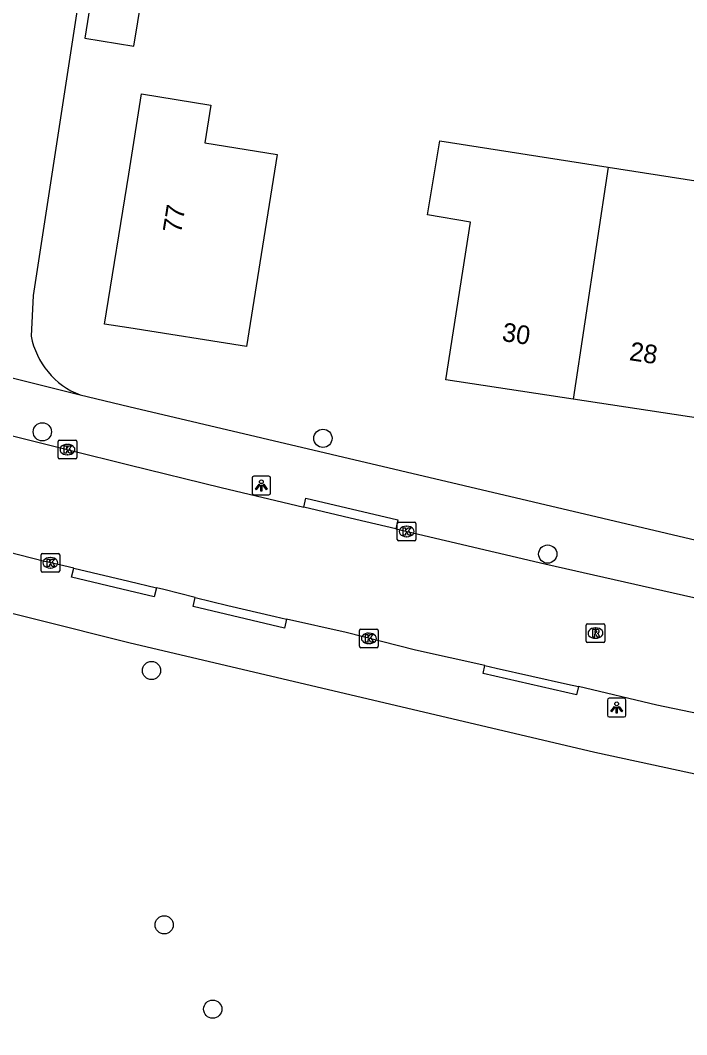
# Model space of a CAD drawing. Extents: x 161486 to 162249, y 379484 to 380829.
# Drawn here: x 161994.2 to 162029.9, y 380361 to 380415.4 of the extents above; entities that cross this region are included whole.
import ezdxf

# ---------------------------------------------------------------- set-up
doc = ezdxf.new("R2010")
doc.units = 0
for name, color, linetype in [('IMGEO_Boom', 7, 'Continuous'), ('IMGEO_Kolk', 7, 'Continuous'), ('IMGEO_Lichtpunt', 7, 'Continuous'), ('IMGEO_Pand', 7, 'Continuous'), ('IMGEO_Pand_nummerreeks', 7, 'Continuous'), ('IMGEO_Rijbaan_lokaal_open', 7, 'Continuous'), ('IMGEO_Rioolput', 7, 'Continuous'), ('IMGEO_Voetpad_open', 7, 'Continuous')]:
    doc.layers.add(name, color=color, linetype=linetype)

msp = doc.modelspace()

# ---------------------------------------------------------------- linework, layer by layer
at = {"layer": 'IMGEO_Boom'}
for centre in [(161995.365, 380393.337), (162010.417, 380392.989), (162022.476, 380386.782), (162001.224, 380380.539), (162001.905, 380366.904), (162004.508, 380362.385)]:
    msp.add_circle(centre, 0.489, dxfattribs=at)
at = {"layer": 'IMGEO_Kolk'}
for p, q in [((161996.291, 380392.884), (161997.143, 380392.884)), ((161996.216, 380391.958), (161996.216, 380392.81)), ((161996.704, 380392.664), (161996.729, 380392.664)), ((161997.217, 380392.81), (161997.217, 380391.958)), ((161997.143, 380391.884), (161996.291, 380391.884)), ((161996.727, 380392.104), (161996.702, 380392.104)), ((162014.407, 380387.569), (162014.407, 380388.421)), ((162014.482, 380388.495), (162015.334, 380388.495)), ((162014.895, 380388.275), (162014.92, 380388.275)), ((162015.408, 380388.421), (162015.408, 380387.569)), ((162015.334, 380387.495), (162014.482, 380387.495)), ((162014.918, 380387.715), (162014.893, 380387.715)), ((161995.3, 380385.889), (161995.3, 380386.741)), ((161995.375, 380386.815), (161996.227, 380386.815)), ((161995.788, 380386.595), (161995.813, 380386.595)), ((161996.301, 380386.741), (161996.301, 380385.889)), ((161996.227, 380385.815), (161995.375, 380385.815)), ((161995.811, 380386.035), (161995.786, 380386.035)), ((162012.381, 380381.837), (162012.381, 380382.689)), ((162012.456, 380382.763), (162013.308, 380382.763)), ((162012.869, 380382.543), (162012.894, 380382.543)), ((162013.382, 380382.689), (162013.382, 380381.837)), ((162012.892, 380381.983), (162012.867, 380381.983)), ((162013.308, 380381.763), (162012.456, 380381.763))]:
    msp.add_line(p, q, dxfattribs=at)
for points in [[(161996.291, 380392.884), (161997.143, 380392.884)], [(161996.216, 380391.958), (161996.216, 380392.81)], [(161996.537, 380392.584), (161996.66, 380392.584), (161996.66, 380392.433), (161996.79, 380392.584), (161996.954, 380392.584), (161996.808, 380392.433), (161996.961, 380392.184), (161996.809, 380392.184), (161996.724, 380392.348), (161996.66, 380392.281), (161996.66, 380392.184), (161996.537, 380392.184), (161996.537, 380392.584)], [(161997.217, 380392.81), (161997.217, 380391.958)], [(161997.143, 380391.884), (161996.291, 380391.884)], [(162014.407, 380387.569), (162014.407, 380388.421)], [(162014.482, 380388.495), (162015.334, 380388.495)], [(162014.728, 380388.195), (162014.851, 380388.195), (162014.851, 380388.044), (162014.981, 380388.195), (162015.145, 380388.195), (162014.999, 380388.044), (162015.152, 380387.795), (162015, 380387.795), (162014.915, 380387.959), (162014.851, 380387.892), (162014.851, 380387.795), (162014.728, 380387.795), (162014.728, 380388.195)], [(162015.408, 380388.421), (162015.408, 380387.569)], [(162015.334, 380387.495), (162014.482, 380387.495)], [(161995.3, 380385.889), (161995.3, 380386.741)], [(161995.375, 380386.815), (161996.227, 380386.815)], [(161995.621, 380386.515), (161995.744, 380386.515), (161995.744, 380386.364), (161995.874, 380386.515), (161996.038, 380386.515), (161995.892, 380386.364), (161996.045, 380386.115), (161995.893, 380386.115), (161995.808, 380386.279), (161995.744, 380386.212), (161995.744, 380386.115), (161995.621, 380386.115), (161995.621, 380386.515)], [(161996.301, 380386.741), (161996.301, 380385.889)], [(161996.227, 380385.815), (161995.375, 380385.815)], [(162012.381, 380381.837), (162012.381, 380382.689)], [(162012.456, 380382.763), (162013.308, 380382.763)], [(162013.382, 380382.689), (162013.382, 380381.837)], [(162012.702, 380382.463), (162012.825, 380382.463), (162012.825, 380382.312), (162012.955, 380382.463), (162013.119, 380382.463), (162012.973, 380382.312), (162013.126, 380382.063), (162012.974, 380382.063), (162012.889, 380382.227), (162012.825, 380382.16), (162012.825, 380382.063), (162012.702, 380382.063), (162012.702, 380382.463)], [(162013.308, 380381.763), (162012.456, 380381.763)]]:
    msp.add_lwpolyline(points, dxfattribs=at)
for centre, start, end in [((161996.293, 380392.808), 91.552, 178.448), ((161996.293, 380392.808), 91.552, 178.448), ((161997.141, 380392.808), 1.552, 88.448), ((161997.141, 380392.808), 1.552, 88.448), ((161996.293, 380391.96), 181.552, 268.448), ((161996.293, 380391.96), 181.552, 268.448), ((161997.141, 380391.96), 271.552, 358.448), ((161997.141, 380391.96), 271.552, 358.448), ((162014.484, 380388.419), 91.552, 178.448), ((162014.484, 380388.419), 91.552, 178.448), ((162015.332, 380388.419), 1.552, 88.448), ((162015.332, 380388.419), 1.552, 88.448), ((162014.484, 380387.571), 181.552, 268.448), ((162014.484, 380387.571), 181.552, 268.448), ((162015.332, 380387.571), 271.552, 358.448), ((162015.332, 380387.571), 271.552, 358.448), ((161995.377, 380386.739), 91.552, 178.448), ((161995.377, 380386.739), 91.552, 178.448), ((161996.225, 380386.739), 1.552, 88.448), ((161996.225, 380386.739), 1.552, 88.448), ((161995.377, 380385.891), 181.552, 268.448), ((161995.377, 380385.891), 181.552, 268.448), ((161996.225, 380385.891), 271.552, 358.448), ((161996.225, 380385.891), 271.552, 358.448), ((162012.458, 380382.687), 91.552, 178.448), ((162012.458, 380382.687), 91.552, 178.448), ((162013.306, 380382.687), 1.552, 88.448), ((162013.306, 380382.687), 1.552, 88.448), ((162012.458, 380381.839), 181.552, 268.448), ((162012.458, 380381.839), 181.552, 268.448), ((162013.306, 380381.839), 271.552, 358.448), ((162013.306, 380381.839), 271.552, 358.448)]:
    msp.add_arc(centre, 0.0765, start, end, dxfattribs=at)
for centre, major_axis, ratio, start_param, end_param in [((161996.703, 380392.384), (-0.387, 0.002), 0.722429, 4.712389, 7.853982), ((161996.728, 380392.384), (-0.39, 0.002), 0.717154, 1.570796, 4.712389), ((162014.894, 380387.995), (-0.387, 0.002), 0.722429, 4.712389, 7.853982), ((162014.919, 380387.995), (-0.39, 0.002), 0.717154, 1.570796, 4.712389), ((161995.787, 380386.315), (-0.387, 0.002), 0.722429, 4.712389, 7.853982), ((161995.812, 380386.315), (-0.39, 0.002), 0.717154, 1.570796, 4.712389), ((162012.868, 380382.263), (-0.387, 0.002), 0.722429, 4.712389, 7.853982), ((162012.893, 380382.263), (-0.39, 0.002), 0.717154, 1.570796, 4.712389)]:
    msp.add_ellipse(centre, major_axis=major_axis, ratio=ratio, start_param=start_param, end_param=end_param, dxfattribs=at)
at = {"layer": 'IMGEO_Lichtpunt'}
for p, q in [((162006.617, 380390.861), (162006.617, 380390.054)), ((162006.617, 380390.861), (162006.617, 380390.054)), ((162007.519, 380390.956), (162006.711, 380390.956)), ((162007.519, 380390.956), (162006.711, 380390.956)), ((162007.613, 380390.054), (162007.613, 380390.861)), ((162007.613, 380390.054), (162007.613, 380390.861)), ((162006.711, 380389.96), (162007.519, 380389.96)), ((162006.711, 380389.96), (162007.519, 380389.96)), ((162025.674, 380378.955), (162025.674, 380378.148)), ((162025.674, 380378.955), (162025.674, 380378.148)), ((162026.576, 380379.05), (162025.768, 380379.05)), ((162026.576, 380379.05), (162025.768, 380379.05)), ((162026.67, 380378.148), (162026.67, 380378.955)), ((162026.67, 380378.148), (162026.67, 380378.955)), ((162025.768, 380378.054), (162026.576, 380378.054)), ((162025.768, 380378.054), (162026.576, 380378.054))]:
    msp.add_line(p, q, dxfattribs=at)
for points in [[(162006.991, 380390.525), (162007.03, 380390.497), (162006.842, 380390.235), (162006.804, 380390.262), (162006.991, 380390.525)], [(162007.093, 380390.477), (162007.14, 380390.477), (162007.14, 380390.155), (162007.093, 380390.155), (162007.093, 380390.477)], [(162007.203, 380390.497), (162007.241, 380390.524), (162007.428, 380390.262), (162007.389, 380390.234), (162007.203, 380390.497)], [(162026.048, 380378.619), (162026.087, 380378.591), (162025.899, 380378.329), (162025.861, 380378.356), (162026.048, 380378.619)], [(162026.15, 380378.571), (162026.197, 380378.571), (162026.197, 380378.249), (162026.15, 380378.249), (162026.15, 380378.571)], [(162026.26, 380378.591), (162026.298, 380378.618), (162026.485, 380378.356), (162026.446, 380378.328), (162026.26, 380378.591)]]:
    msp.add_lwpolyline(points, dxfattribs=at)
for centre in [(162007.116, 380390.659), (162026.173, 380378.753)]:
    msp.add_circle(centre, 0.0994, dxfattribs=at)
for centre, start, end in [((162006.711, 380390.861), 90, 180), ((162006.711, 380390.861), 90, 180), ((162007.519, 380390.861), 0, 90), ((162007.519, 380390.861), 0, 90), ((162006.711, 380390.054), 180, 270), ((162006.711, 380390.054), 180, 270), ((162007.519, 380390.054), 270, 0), ((162007.519, 380390.054), 270, 360), ((162025.768, 380378.955), 90, 180), ((162025.768, 380378.955), 90, 180), ((162026.576, 380378.955), 0, 90), ((162026.576, 380378.955), 0, 90), ((162025.768, 380378.148), 180, 270), ((162025.768, 380378.148), 180, 270), ((162026.576, 380378.148), 270, 0), ((162026.576, 380378.148), 270, 360)]:
    msp.add_arc(centre, 0.0946, start, end, dxfattribs=at)
at = {"layer": 'IMGEO_Pand'}
for points in [[(162000.28, 380414.018), (162000.894, 380417.837), (161998.259, 380418.26), (161997.645, 380414.442), (162000.28, 380414.018)], [(162007.108, 380402.844), (162006.314, 380397.907), (162000, 380398.907), (161998.709, 380399.115), (162000, 380407.143), (162000.692, 380411.45), (162004.41, 380410.852), (162004.085, 380408.833), (162007.97, 380408.208), (162007.108, 380402.844)], [(162023.835, 380395.085), (162017.005, 380396.115), (162018.338, 380404.581), (162016.03, 380404.966), (162016.693, 380408.941), (162025.713, 380407.533)], [(162025.713, 380407.533), (162034.554, 380406.153), (162033.958, 380402.207), (162031.94, 380402.511), (162031.411, 380399.001), (162030.665, 380394.056), (162023.835, 380395.085)], [(162025.713, 380407.533), (162023.835, 380395.085)]]:
    msp.add_lwpolyline(points, dxfattribs=at)
at = {"layer": 'IMGEO_Rijbaan_lokaal_open'}
for points in [[(161992.46, 380393.44), (161995.413, 380392.705), (161996.835, 380392.354), (162000, 380391.572), (162004.962, 380390.345), (162009.394, 380389.294)], [(161997.05, 380386.022), (161995.688, 380386.342), (161995.492, 380386.388), (161992.812, 380387.055), (161990.183, 380387.733), (161986.973, 380388.57), (161983.884, 380389.337), (161982.489, 380389.727)], [(162014.33, 380388.129), (162012.189, 380388.632), (162009.394, 380389.294)], [(162014.33, 380388.129), (162022.326, 380386.252), (162029.194, 380384.698), (162030.861, 380384.328)], [(161997.05, 380386.022), (162000, 380385.329), (162001.484, 380384.978)], [(162003.566, 380384.463), (162001.88, 380384.884), (162001.484, 380384.978)], [(162003.566, 380384.463), (162005.309, 380384.028), (162007.858, 380383.44), (162008.469, 380383.301)], [(162019.103, 380380.805), (162015.375, 380381.627), (162011.667, 380382.574), (162008.469, 380383.301)], [(162019.103, 380380.805), (162019.704, 380380.672), (162023.533, 380379.815), (162024.127, 380379.675)], [(162033.585, 380377.579), (162031.94, 380377.933), (162028.321, 380378.69), (162024.127, 380379.675)]]:
    msp.add_lwpolyline(points, dxfattribs=at)
at = {"layer": 'IMGEO_Rioolput'}
for p, q in [((162024.536, 380382.119), (162024.536, 380382.971)), ((162024.611, 380383.045), (162025.463, 380383.045)), ((162025.024, 380382.825), (162025.049, 380382.825)), ((162025.537, 380382.971), (162025.537, 380382.119)), ((162025.463, 380382.045), (162024.611, 380382.045)), ((162025.047, 380382.265), (162025.022, 380382.265))]:
    msp.add_line(p, q, dxfattribs=at)
for points in [[(162024.536, 380382.119), (162024.536, 380382.971)], [(162024.611, 380383.045), (162025.463, 380383.045)], [(162025.125, 380382.743), (162024.873, 380382.745), (162024.873, 380382.345)], [(162025.051, 380382.664), (162024.997, 380382.664), (162024.997, 380382.583)], [(162024.997, 380382.583), (162025.049, 380382.583)], [(162025.537, 380382.971), (162025.537, 380382.119)], [(162025.463, 380382.045), (162024.611, 380382.045)], [(162024.873, 380382.345), (162024.997, 380382.345), (162024.997, 380382.507), (162025.008, 380382.507)], [(162025.055, 380382.478), (162025.126, 380382.345), (162025.266, 380382.345), (162025.201, 380382.471)]]:
    msp.add_lwpolyline(points, dxfattribs=at)
for centre, radius, start, end in [((162024.613, 380382.969), 0.0765, 91.552, 178.448), ((162024.613, 380382.969), 0.0765, 91.552, 178.448), ((162025.033, 380382.772), 0.19, 274.7715, 282.9687), ((162025.057, 380382.568), 0.0964, 77.0061, 93.1865), ((162025.071, 380382.625), 0.0378, 276.6634, 79.6772), ((162025.124, 380382.633), 0.109, 350.3612, 89.416), ((162025.122, 380382.633), 0.112, 277.5842, 350.9817), ((162025.106, 380382.418), 0.108, 29.5134, 73.7905), ((162025.461, 380382.969), 0.0765, 1.552, 88.448), ((162025.461, 380382.969), 0.0765, 1.552, 88.448), ((162024.613, 380382.121), 0.0765, 181.552, 268.448), ((162024.613, 380382.121), 0.0765, 181.552, 268.448), ((162025.007, 380382.454), 0.0533, 26.0293, 88.6989), ((162025.461, 380382.121), 0.0765, 271.552, 358.448), ((162025.461, 380382.121), 0.0765, 271.552, 358.448)]:
    msp.add_arc(centre, radius, start, end, dxfattribs=at)
for centre, major_axis, ratio, start_param, end_param in [((162025.023, 380382.545), (-0.387, 0.002), 0.722429, 4.712389, 7.853982), ((162025.048, 380382.545), (-0.39, 0.002), 0.717154, 1.570796, 4.712389)]:
    msp.add_ellipse(centre, major_axis=major_axis, ratio=ratio, start_param=start_param, end_param=end_param, dxfattribs=at)
at = {"layer": 'IMGEO_Voetpad_open'}
for points in [[(162009.269, 380494.234), (162000, 380433.985), (161994.885, 380400.652), (161994.764, 380398.467)], [(162198.701, 380353.085), (162194.98, 380353.343), (162177.85, 380354.254), (162167.435, 380355.075), (162143.228, 380356.612), (162124.747, 380358.414), (162101.438, 380361.321), (162078.957, 380365.04), (162051.567, 380370.414), (162025.006, 380376.148), (162000, 380382.025), (161995.099, 380383.252), (161959.315, 380392.214), (161910.21, 380403.651), (161910.18, 380403.657)], [(161991.274, 380396.858), (161994.606, 380396.016), (161997.399, 380395.311)], [(161997.399, 380395.311), (162000, 380394.69), (162043.415, 380384.478), (162054.712, 380382.262)], [(162009.394, 380389.294), (162009.508, 380389.78), (162014.444, 380388.615), (162014.33, 380388.129)], [(162001.484, 380384.978), (162001.37, 380384.492), (162000, 380384.815), (161996.936, 380385.537), (161997.05, 380386.022)], [(162008.469, 380383.301), (162008.354, 380382.815), (162003.451, 380383.977), (162003.566, 380384.463)], [(162024.127, 380379.675), (162024.026, 380379.233), (162019.006, 380380.379), (162019.103, 380380.805)]]:
    msp.add_lwpolyline(points, dxfattribs=at)
msp.add_arc((161998.934, 380399.271), 4.247, 190.9075, 248.8107, dxfattribs=at)

# ---------------------------------------------------------------- texts
at = {"layer": 'IMGEO_Pand_nummerreeks'}
for s, rotation, p in [('77', 80.8672, (162002.809, 380403.946)), ('30', 351.4282, (162019.981, 380398.214)), ('28', 351.4282, (162026.811, 380397.184))]:
    msp.add_text(s, height=1, rotation=rotation, dxfattribs=at).set_placement(p)

doc.saveas('drawing.dxf')
